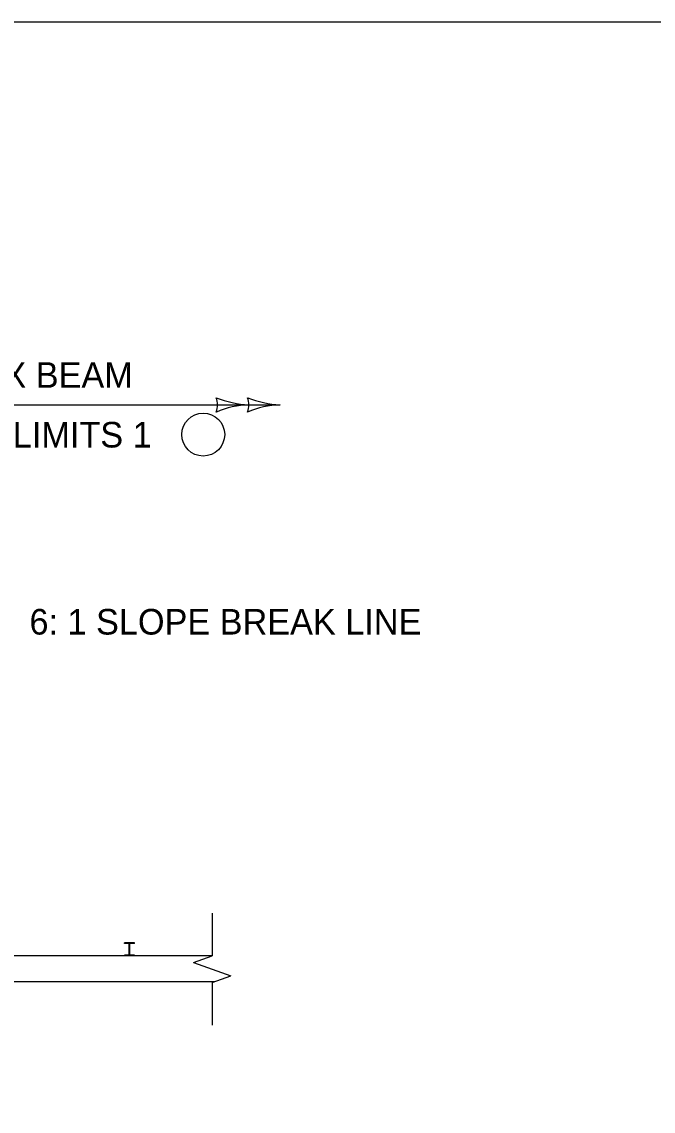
# Model space of a CAD drawing. Extents: x 49991.4 to 50021, y 49987.6 to 50011.4.
# Drawn here: x 50007.884 to 50009.364, y 49996.445 to 49998.999 of the extents above; entities that cross this region are included whole.
import ezdxf

# ---------------------------------------------------------------- set-up
doc = ezdxf.new("R2010")
doc.units = 0
for name, color, linetype in [('Level 1', 7, 'Continuous'), ('Level 2', 7, 'Continuous'), ('Level 3', 7, 'Continuous'), ('Level 6', 7, 'Continuous')]:
    doc.layers.add(name, color=color, linetype=linetype)

msp = doc.modelspace()

# ---------------------------------------------------------------- linework, layer by layer
at = {"layer": 'Level 1'}
for p, q in [((50008.1482, 49996.8397), (50008.1246, 49996.8397)), ((50008.1246, 49996.8381), (50008.1246, 49996.8397)), ((50008.1348, 49996.8381), (50008.1246, 49996.8381)), ((50008.1356, 49996.8116), (50008.1356, 49996.8373)), ((50008.1372, 49996.8116), (50008.1372, 49996.8373)), ((50008.1482, 49996.8381), (50008.138, 49996.8381)), ((50008.1482, 49996.8381), (50008.1482, 49996.8397)), ((50008.33, 49996.8092), (50007.0484, 49996.8092)), ((50008.1246, 49996.8092), (50008.1246, 49996.8108)), ((50008.1348, 49996.8108), (50008.1246, 49996.8108)), ((50008.1482, 49996.8108), (50008.138, 49996.8108)), ((50008.1482, 49996.8092), (50008.1482, 49996.8108)), ((50008.3345, 49996.7484), (50007.0484, 49996.7484))]:
    msp.add_line(p, q, dxfattribs=at)
msp.add_lwpolyline([(49999.3835, 49998.9992), (50016.7501, 49998.9992), (50016.7501, 49987.7988), (49999.3835, 49987.7988)], close=True, dxfattribs=at)
for centre, start, end in [((50008.1348, 49996.8373), 0, 90), ((50008.138, 49996.8373), 90, 180), ((50008.1348, 49996.8116), 270, 0), ((50008.138, 49996.8116), 180, 270)]:
    msp.add_arc(centre, 0.0008, start, end, dxfattribs=at)
at = {"layer": 'Level 2'}
msp.add_circle((50008.3092, 49998.0315), 0.0503, dxfattribs=at)
at = {"layer": 'Level 3'}
msp.add_line((50007.0384, 49998.1012), (50008.4895, 49998.1012), dxfattribs=at)
for centre, radius, start, end in [((50008.2878, 49998.1012), 0.0548, 342.1388, 17.8612), ((50008.4275, 49998.3339), 0.233, 247.9228, 267.1727), ((50008.3612, 49998.1012), 0.0548, 342.1388, 17.8612), ((50008.501, 49998.3339), 0.233, 247.9228, 267.1727), ((50008.4252, 49997.8791), 0.2223, 92.3605, 112.544), ((50008.4986, 49997.8791), 0.2223, 92.3605, 112.544)]:
    msp.add_arc(centre, radius, start, end, dxfattribs=at)
at = {"layer": 'Level 6'}
for p, q in [((50008.33, 49996.9092), (50008.33, 49996.8092)), ((50008.2862, 49996.7939), (50008.33, 49996.8092)), ((50008.2862, 49996.7939), (50008.33, 49996.7782)), ((50008.33, 49996.7782), (50008.3741, 49996.7626)), ((50008.33, 49996.7468), (50008.3741, 49996.7626)), ((50008.33, 49996.7468), (50008.33, 49996.6468))]:
    msp.add_line(p, q, dxfattribs=at)

# ---------------------------------------------------------------- texts
at = {"layer": 'Level 2'}
for s, p in [('STANDARD BOX BEAM', (50007.2614, 49998.1412)), ('GUARDRAIL PAY LIMITS 1', (50007.1897, 49998.0012))]:
    msp.add_text(s, height=0.06, dxfattribs=at).set_placement(p)
msp.add_text('6: 1 SLOPE BREAK LINE', height=0.06, rotation=360, dxfattribs=at).set_placement((50007.9019, 49997.5627))

doc.saveas('drawing.dxf')
